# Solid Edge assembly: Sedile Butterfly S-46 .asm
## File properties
Title: SEDILE BUTTERFLY S-46
Author: DESYS
Template: Iso Assembly.asm
Last saved by: PIM_1
Revision: 5
Application: Solid Edge
Tipo di contenuto documento: 1
Document Number: 4010
Revision: 0
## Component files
Sedile Butterfly S-46.par
Sedile Butterfly S-46 Forato.par
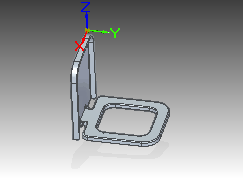
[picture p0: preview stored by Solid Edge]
